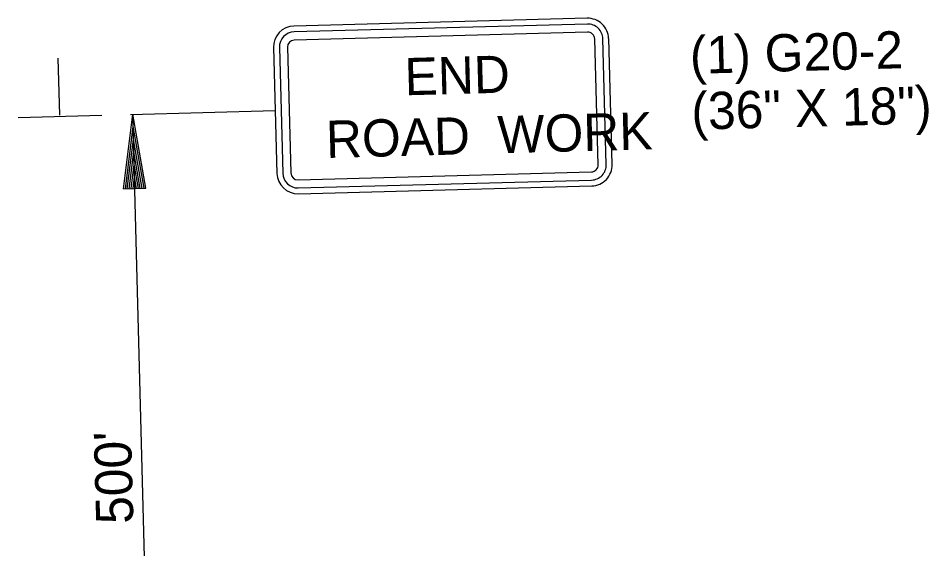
# Model space of a CAD drawing. Extents: x 1930579 to 1931593, y 596452 to 598537.
# Drawn here: x 1930948 to 1931094.7, y 598094.8 to 598180.2 of the extents above; entities that cross this region are included whole.
import ezdxf

# ---------------------------------------------------------------- set-up
doc = ezdxf.new("R2010")
doc.units = 0
for name, color, linetype in [('P_TC_Signs_Temporary', 7, 'Continuous'), ('R_Annotation', 7, 'Continuous'), ('R_Draft', 7, 'Continuous')]:
    doc.layers.add(name, color=color, linetype=linetype)

msp = doc.modelspace()

# ---------------------------------------------------------------- linework, layer by layer
at = {"layer": 'P_TC_Signs_Temporary'}
for p, q in [((1931039.63, 598180.24), (1930992.4, 598178.97)), ((1931039.66, 598179.3), (1930992.42, 598178.03)), ((1931039.69, 598177.99), (1930992.46, 598176.72)), ((1931041.39, 598156.65), (1931040.85, 598176.89)), ((1931042.7, 598156.69), (1931042.16, 598176.93)), ((1931043.64, 598156.71), (1931043.1, 598176.95)), ((1930989.12, 598175.5), (1930989.66, 598155.26)), ((1930990.05, 598175.53), (1930990.6, 598155.29)), ((1930991.37, 598175.56), (1930991.91, 598155.32)), ((1930993.06, 598154.23), (1931040.3, 598155.5)), ((1930993.1, 598152.92), (1931040.33, 598154.18)), ((1930993.12, 598151.98), (1931040.36, 598153.25))]:
    msp.add_line(p, q, dxfattribs=at)
for centre, radius, start, end in [((1931039.72, 598176.86), 3.37, 1.5377, 91.5377), ((1930992.49, 598175.59), 3.38, 91.5377, 181.5377), ((1930992.49, 598175.59), 2.44, 91.5377, 181.5377), ((1931039.72, 598176.86), 2.44, 1.5377, 91.5377), ((1930992.49, 598175.59), 1.13, 91.5377, 181.5377), ((1931039.72, 598176.86), 1.13, 1.5377, 91.5377), ((1931040.27, 598156.62), 1.13, 271.5377, 1.5377), ((1931040.27, 598156.62), 2.44, 271.5377, 1.5377), ((1931040.27, 598156.62), 3.38, 271.5377, 1.5377), ((1930993.03, 598155.35), 3.37, 181.5377, 271.5377), ((1930993.03, 598155.35), 2.44, 181.5377, 271.5377), ((1930993.03, 598155.35), 1.13, 181.5377, 271.5377)]:
    msp.add_arc(centre, radius, start, end, dxfattribs=at)
at = {"layer": 'R_Draft'}
for p, q in [((1930954.68, 598164.65), (1930954.43, 598173.83)), ((1930966.1, 598164.76), (1930989.39, 598165.38)), ((1930947.99, 598164.27), (1930961.45, 598164.63)), ((1930964.96, 598152.76), (1930966.44, 598164.78)), ((1930969.72, 598042.45), (1930966.44, 598164.78)), ((1930968.55, 598152.86), (1930966.44, 598164.78)), ((1930965.26, 598152.77), (1930966.49, 598162.78)), ((1930968.25, 598152.85), (1930966.49, 598162.78)), ((1930965.56, 598152.78), (1930966.54, 598160.72)), ((1930967.95, 598152.84), (1930966.54, 598160.72)), ((1930965.86, 598152.79), (1930966.6, 598158.73)), ((1930967.65, 598152.83), (1930966.6, 598158.73)), ((1930966.18, 598152.8), (1930966.65, 598156.7)), ((1930967.34, 598152.83), (1930966.65, 598156.7)), ((1930966.48, 598152.8), (1930966.71, 598154.7)), ((1930967.04, 598152.82), (1930966.71, 598154.7)), ((1930964.96, 598152.76), (1930968.55, 598152.86))]:
    msp.add_line(p, q, dxfattribs=at)

# ---------------------------------------------------------------- texts
at = {"layer": 'P_TC_Signs_Temporary'}
for s, p in [('END', (1931010.3, 598167.82)), ('ROAD  WORK', (1930997.64, 598157.73))]:
    msp.add_text(s, height=6, rotation=1.5377, dxfattribs=at).set_placement(p)
at = {"layer": 'R_Annotation'}
for s, p in [('(1) G20-2', (1931056.25, 598171.27)), ('(36" X 18")', (1931056.49, 598162.27))]:
    msp.add_text(s, height=6, rotation=1.5377, dxfattribs=at).set_placement(p)
at = {"layer": 'R_Draft'}
msp.add_text("500'", height=6, rotation=91.5377, dxfattribs=at).set_placement((1930966.55, 598098.89))

doc.saveas('drawing.dxf')
